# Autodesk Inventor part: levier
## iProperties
Shininess: 21.0
Length Units: 11269
Angle Units: 11279
Time Units: 11290
Mass Units: 11283
Length Display Precision: 3
Angle Display Precision: 2
Compacted: True
Created: 2001-12
Part Number: levier
Material: Par défaut
Document SubType Name: Modélisation
Designer: pichon
Density: 0.0
Volumn: 0.0
Area: 0.0
PropertySet Name: Model Information
Control State: 0
Master: False
Checked Out: False
Author: pichon
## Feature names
1. Extrusion1
2. Extrusion2
3. Congé1 [Fillet]
4. Extrusion3
5. Extrusion4
6. Congé2 [Fillet]
7. Coque1
8. Révolution2 [Revolution]
9. Congé3 [Fillet]
10. Extrusion5
11. Symétrie1 [Mirror]
12. Extrusion6
